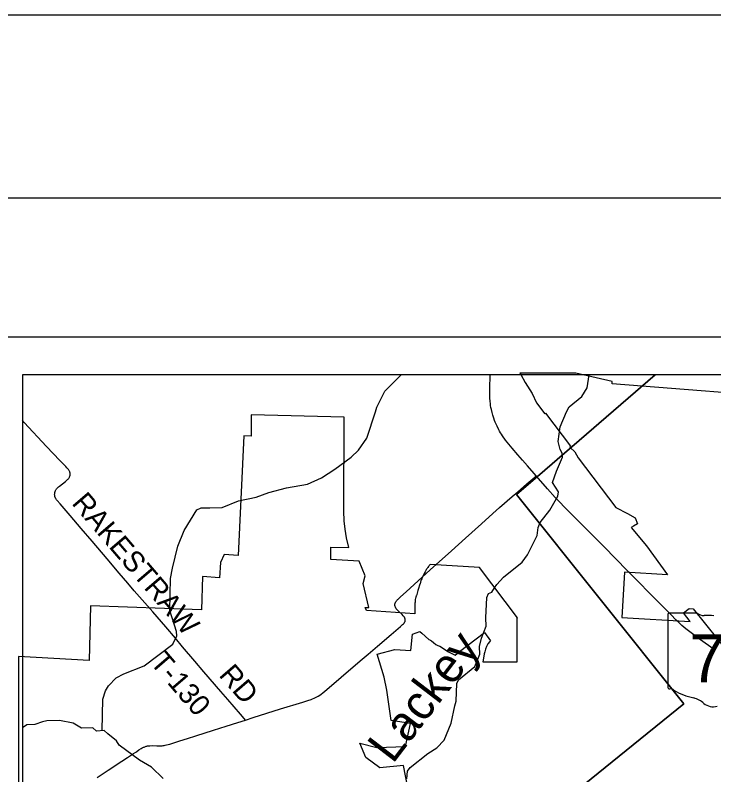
# Model space of a CAD drawing. Extents: x -5.4 to 49.9, y 13.2 to 48.4.
# Drawn here: x 26.257 to 28.171, y 46.348 to 48.429 of the extents above; entities that cross this region are included whole.
import ezdxf

# ---------------------------------------------------------------- set-up
doc = ezdxf.new("R2010")
doc.units = 0
for name, color, linetype in [('GM_X_Corporation', 7, 'Continuous'), ('GM_X_Minor_River', 7, 'Continuous'), ('GM_X_Minor_River_Text', 7, 'Continuous'), ('GM_X_State_Location', 7, 'Continuous'), ('GM_X_State_Route', 7, 'Continuous'), ('GM_X_State_Shield', 7, 'Continuous'), ('GM_X_Township', 7, 'Continuous'), ('GM_X_Township_Road', 7, 'Continuous'), ('GM_X_Township_Road_Text', 7, 'Continuous'), ('SH_Border', 7, 'Continuous'), ('SH_Cut_Line', 7, 'Continuous'), ('SH_Data', 7, 'Continuous')]:
    doc.layers.add(name, color=color, linetype=linetype)

msp = doc.modelspace()

# ---------------------------------------------------------------- linework, layer by layer
at = {"layer": 'GM_X_Corporation'}
for p, q in [((27.7927, 47.4483), (27.6398, 47.4483)), ((26.2655, 46.6728), (26.2655, 44.9832))]:
    msp.add_line(p, q, dxfattribs=at)
for points in [[(27.6398, 47.4483), (27.6425, 47.4443), (27.6547, 47.4231), (27.6735, 47.3931), (27.6855, 47.3674), (27.7081, 47.3374), (27.7103, 47.3392), (27.7787, 47.2485), (27.7764, 47.2467), (27.7778, 47.2449), (27.7899, 47.2332), (27.7998, 47.2168), (27.9024, 47.0807), (27.9348, 47.0642), (27.9553, 47.0524), (27.962, 47.0357), (27.951, 47.0294), (27.9448, 47.0254), (27.9863, 46.9755), (28.0445, 46.8962), (27.9267, 46.9035), (27.9193, 46.7796), (28.1062, 46.7686), (28.0885, 46.792), (28.1041, 46.8038), (28.1146, 46.8031), (28.2164, 46.6772)], [(28.4455, 47.4483), (28.4446, 47.4411), (28.539, 47.4366), (28.5355, 47.3724), (28.4268, 47.3772), (27.8922, 47.4191), (27.8926, 47.4253), (27.7927, 47.4483)], [(27.3326, 46.3129), (27.321, 46.3737), (27.2558, 46.3673), (27.218, 46.3961), (27.201, 46.4349), (27.2475, 46.4233), (27.3268, 46.4261), (27.3402, 46.4893), (27.2874, 46.4967), (27.2751, 46.5806), (27.2676, 46.6162), (27.249, 46.6786), (27.2972, 46.6911), (27.3408, 46.6889), (27.3451, 46.7337), (27.3657, 46.7408), (27.3713, 46.7363), (27.3907, 46.7193), (27.3951, 46.7167), (27.3973, 46.7152), (27.4028, 46.7106), (27.4099, 46.7052), (27.4153, 46.7025), (27.42, 46.7004), (27.4444, 46.6856), (27.462, 46.6763), (27.4746, 46.6863), (27.5429, 46.7377), (27.5592, 46.7155), (27.5574, 46.7138), (27.5522, 46.7075), (27.5479, 46.6997), (27.5454, 46.6925), (27.5435, 46.6856), (27.5423, 46.6795), (27.5411, 46.6734), (27.538, 46.6578), (27.6326, 46.658), (27.6322, 46.7773), (27.6336, 46.7784), (27.5294, 46.9164), (27.3944, 46.9247), (27.3914, 46.9214), (27.3902, 46.92), (27.3892, 46.9186), (27.3878, 46.9164), (27.3867, 46.9148), (27.3859, 46.9137), (27.3842, 46.9117), (27.3833, 46.9105), (27.383, 46.91), (27.3819, 46.908), (27.381, 46.9063), (27.3802, 46.9046), (27.3776, 46.8998), (27.3766, 46.898), (27.3758, 46.8962), (27.3749, 46.894), (27.3723, 46.8875), (27.3713, 46.8854), (27.3697, 46.8819), (27.3688, 46.8797), (27.3684, 46.8786), (27.3678, 46.877), (27.3671, 46.8745), (27.3665, 46.8726), (27.3651, 46.8675), (27.3622, 46.8587), (27.3604, 46.853), (27.3594, 46.8497), (27.3584, 46.8459), (27.3574, 46.8426), (27.357, 46.8415), (27.3563, 46.8396), (27.3557, 46.8384), (27.3555, 46.8377), (27.3552, 46.8371), (27.3548, 46.8359), (27.3544, 46.8344), (27.3539, 46.8318), (27.3533, 46.8285), (27.353, 46.8262), (27.3529, 46.826), (27.3527, 46.8243), (27.3524, 46.8209), (27.3522, 46.8181), (27.3521, 46.8156), (27.3518, 46.7891), (27.2197, 46.7981), (27.2162, 46.8065), (27.2255, 46.8068), (27.2103, 46.8726), (27.2154, 46.8931), (27.1997, 46.9337), (27.1217, 46.9382), (27.1219, 46.9716), (27.1713, 46.971), (27.165, 46.9976), (27.1609, 47.0207), (27.1584, 47.0438), (27.1575, 47.0708), (27.158, 47.3276), (26.9037, 47.334), (26.9031, 47.2756), (26.8837, 47.2767), (26.8681, 46.9489), (26.8297, 46.9517), (26.8196, 46.9296), (26.8166, 46.8878), (26.7705, 46.8912), (26.7674, 46.8003), (26.4629, 46.8115), (26.4596, 46.6617), (26.2655, 46.6728)]]:
    msp.add_lwpolyline(points, dxfattribs=at)
at = {"layer": 'GM_X_Minor_River'}
for points in [[(26.4952, 46.4695), (26.4969, 46.5551), (26.5041, 46.5781), (26.5123, 46.5921), (26.5331, 46.6138), (26.5545, 46.6245), (26.6102, 46.6472), (26.6892, 46.706), (26.7002, 46.7293), (26.6992, 46.7407), (26.6804, 46.798), (26.6821, 46.8864), (26.6875, 46.9144), (26.7028, 46.9746), (26.7201, 47.0172), (26.7548, 47.074), (26.7666, 47.0799), (26.7787, 47.0797), (26.7905, 47.0799), (26.8243, 47.0809), (26.8689, 47.0985), (26.9176, 47.1084), (26.9519, 47.1211), (27.0006, 47.134), (27.0577, 47.1442), (27.0962, 47.1618), (27.1326, 47.1852), (27.1779, 47.2183), (27.1975, 47.2377), (27.2208, 47.2704), (27.2442, 47.3429), (27.2482, 47.3554), (27.2701, 47.3991), (27.3148, 47.4437)], [(27.7452, 47.1236), (27.7289, 47.1485), (27.7404, 47.1802), (27.7562, 47.2187), (27.7556, 47.2289), (27.75, 47.2393), (27.7447, 47.261), (27.7498, 47.3015), (27.7675, 47.3426), (27.7746, 47.3562), (27.8095, 47.3841), (27.8243, 47.4078), (27.8294, 47.4437)], [(27.3297, 46.3375), (27.3316, 46.3579), (27.3389, 46.3685), (27.3877, 46.4065), (27.4122, 46.422), (27.4326, 46.4434), (27.4511, 46.4898), (27.4617, 46.5371), (27.4653, 46.55), (27.4672, 46.5982), (27.4719, 46.6087), (27.5161, 46.6453), (27.5302, 46.6785), (27.529, 46.7001), (27.5343, 46.7228), (27.547, 46.7553), (27.5462, 46.7785), (27.5489, 46.8338), (27.5536, 46.8452), (27.5632, 46.8488), (27.5706, 46.8601), (27.5768, 46.8699), (27.5953, 46.8893), (27.6463, 46.9307), (27.6611, 46.951), (27.6869, 47.0037), (27.6903, 47.0261), (27.6958, 47.0393), (27.7217, 47.0731), (27.7435, 47.1118), (27.7452, 47.1236)], [(26.6623, 46.3384), (26.6302, 46.3697), (26.5975, 46.388), (26.542, 46.4299), (26.5346, 46.441), (26.511, 46.4607), (26.5005, 46.47), (26.4796, 46.468), (26.4695, 46.4773), (26.4384, 46.4762), (26.4159, 46.4895), (26.3785, 46.4969), (26.3439, 46.4963), (26.3321, 46.4938), (26.3108, 46.4865), (26.2888, 46.485), (26.2771, 46.4766)]]:
    msp.add_lwpolyline(points, dxfattribs=at)
at = {"layer": 'GM_X_State_Route'}
for points in [[(27.6472, 47.2101), (27.6344, 47.2246), (27.6185, 47.2429), (27.6094, 47.2539), (27.6007, 47.2652), (27.5922, 47.2767), (27.5891, 47.2812), (27.5869, 47.285), (27.5842, 47.2896), (27.5821, 47.2936), (27.5772, 47.3036), (27.5745, 47.3091), (27.5725, 47.3141), (27.5704, 47.319), (27.5683, 47.3248), (27.5656, 47.3329), (27.5635, 47.3407), (27.5616, 47.3491), (27.5605, 47.3547), (27.5597, 47.3601), (27.5591, 47.3652), (27.5586, 47.3706), (27.5578, 47.3811), (27.5574, 47.3874), (27.5574, 47.3935), (27.5574, 47.4096), (27.5585, 47.4388), (27.5587, 47.4437)], [(28.1759, 46.6887), (28.1286, 46.723), (28.1056, 46.7399), (28.0948, 46.7483), (28.0838, 46.7573), (28.075, 46.7652), (28.0683, 46.7716), (28.053, 46.787), (28.0233, 46.8171), (27.9888, 46.852), (27.9711, 46.8703), (27.9348, 46.9069), (27.8694, 46.9734), (27.8231, 47.0203), (27.7914, 47.0518), (27.7643, 47.0792), (27.7473, 47.0965), (27.7364, 47.1083), (27.7154, 47.132), (27.6848, 47.1673), (27.6791, 47.1738), (27.6607, 47.1948), (27.6472, 47.2101)]]:
    msp.add_lwpolyline(points, dxfattribs=at)
at = {"layer": 'GM_X_State_Shield'}
for p, q in [((28.1254, 46.791), (28.0482, 46.791)), ((28.0456, 46.7875), (28.0456, 46.5874))]:
    msp.add_line(p, q, dxfattribs=at)
for centre, radius, start, end in [((28.0486, 46.788), 0.00305, 98.1301, 188.1301), ((28.1438, 46.8142), 0.0296, 231.6195, 271.1119), ((28.1536, 46.6786), 0.1064, 80.4867, 94.9883), ((28.0486, 46.587), 0.00308, 171.9584, 258.3066), ((28.0491, 46.6075), 0.0235, 267.339, 280.6039), ((28.0539, 46.5759), 0.00848, 29.7484, 93.2717), ((28.161, 46.7557), 0.2019, 240.4129, 257.1985), ((28.1008, 46.4975), 0.0632, 47.1842, 75.836), ((28.1691, 46.5749), 0.0401, 230.7004, 286.2918)]:
    msp.add_arc(centre, radius, start, end, dxfattribs=at)
at = {"layer": 'GM_X_Township'}
for points in [[(28.0105, 47.4437), (26.2771, 47.4437), (26.2771, 45.1783)], [(26.2771, 45.1783), (26.3273, 45.1524), (26.3551, 45.1388), (27.3666, 45.9579), (27.3995, 45.9845), (28.089, 46.5424), (27.6308, 47.1161), (27.6499, 47.1327), (27.6877, 47.1657), (28.0105, 47.4437)], [(28.0105, 47.4437), (27.6877, 47.1657), (27.6499, 47.1327), (27.6308, 47.1161), (28.089, 46.5424), (27.3995, 45.9845), (27.4216, 45.9826), (27.5161, 45.979), (27.573, 45.9769), (27.6274, 45.9769), (27.7195, 46.0028), (27.6935, 45.0509), (27.691, 44.9621), (27.6878, 44.8437), (27.7914, 44.8377), (29.42, 44.7443), (29.8881, 44.7175), (31.3945, 44.5822), (32.3292, 44.4982), (33.0771, 44.431)], [(33.0771, 44.431), (33.0771, 47.4437), (28.0105, 47.4437)]]:
    msp.add_lwpolyline(points, dxfattribs=at)
at = {"layer": 'GM_X_Township_Road'}
for points in [[(26.8879, 46.4983), (26.8842, 46.5026), (26.8743, 46.5145), (26.8398, 46.5545), (26.8207, 46.5766), (26.7741, 46.6308), (26.7494, 46.6596), (26.7155, 46.6992), (26.6957, 46.7224), (26.6696, 46.7532), (26.6338, 46.7945), (26.6049, 46.8279), (26.5832, 46.8526), (26.5653, 46.8733), (26.542, 46.9008), (26.509, 46.9396), (26.4676, 46.9884), (26.4376, 47.0233), (26.4077, 47.0582), (26.3797, 47.0907), (26.3719, 47.0996), (26.3702, 47.1017), (26.369, 47.1033), (26.3678, 47.1052), (26.3673, 47.1062), (26.3669, 47.107), (26.3665, 47.1081), (26.3661, 47.1091), (26.3658, 47.11), (26.3656, 47.111), (26.3654, 47.112), (26.3652, 47.1131), (26.3651, 47.1146), (26.365, 47.116), (26.365, 47.1174), (26.3651, 47.1188), (26.3652, 47.1201), (26.3654, 47.1213), (26.3656, 47.1225), (26.366, 47.1238), (26.3664, 47.1248), (26.3669, 47.1259), (26.3676, 47.1273), (26.3684, 47.1287), (26.3692, 47.13), (26.3701, 47.1312), (26.371, 47.1323), (26.372, 47.1335), (26.374, 47.1355), (26.3759, 47.1372), (26.3782, 47.1392), (26.3945, 47.1517), (26.3983, 47.1549), (26.4003, 47.1568), (26.4018, 47.1583), (26.4029, 47.1596), (26.4038, 47.1608), (26.4045, 47.1619), (26.4053, 47.1633), (26.406, 47.1646), (26.4065, 47.166), (26.4068, 47.1671), (26.4071, 47.1684), (26.4073, 47.1697), (26.4073, 47.1711), (26.4073, 47.1725), (26.4073, 47.1738), (26.4071, 47.1751), (26.4069, 47.1762), (26.4066, 47.1775), (26.4062, 47.1786), (26.4056, 47.1799), (26.405, 47.181), (26.404, 47.1826), (26.4025, 47.1844), (26.4004, 47.1871), (26.3985, 47.1893), (26.3955, 47.1924), (26.3938, 47.1942), (26.3904, 47.1978), (26.3792, 47.2096), (26.3429, 47.2479), (26.2818, 47.3133), (26.2771, 47.3183)], [(27.6339, 47.1238), (27.6585, 47.145), (27.6803, 47.1635), (27.6848, 47.1673)], [(26.8879, 46.4983), (26.9089, 46.505), (26.9835, 46.5287), (27.0447, 46.5475), (27.0589, 46.5519), (27.0678, 46.5548), (27.0719, 46.5564), (27.0759, 46.5581), (27.0798, 46.5599), (27.0837, 46.5618), (27.0872, 46.564), (27.0915, 46.5669), (27.0951, 46.5695), (27.1, 46.5732), (27.1111, 46.5822), (27.1502, 46.6159), (27.2024, 46.6609), (27.2237, 46.6791), (27.2493, 46.7007), (27.2871, 46.733), (27.3128, 46.7545), (27.3166, 46.7578), (27.3184, 46.7596), (27.3207, 46.7617), (27.3217, 46.7629), (27.3224, 46.7639), (27.3233, 46.7652), (27.3239, 46.7661), (27.3245, 46.7673), (27.325, 46.7685), (27.3254, 46.7696), (27.3256, 46.7708), (27.3258, 46.7718), (27.3258, 46.7728), (27.3257, 46.7739), (27.3256, 46.7749), (27.3253, 46.7758), (27.3249, 46.7768), (27.3244, 46.7779), (27.3238, 46.7789), (27.3232, 46.7799), (27.3224, 46.7811), (27.3211, 46.7826), (27.3199, 46.7839), (27.3168, 46.787), (27.3083, 46.7952), (27.3043, 46.7992), (27.3027, 46.8011), (27.3012, 46.8029), (27.3004, 46.8042), (27.2996, 46.8054), (27.299, 46.8066), (27.2985, 46.8078), (27.2981, 46.809), (27.2978, 46.81), (27.2975, 46.8111), (27.2974, 46.8127), (27.2974, 46.8141), (27.2974, 46.8153), (27.2975, 46.8164), (27.2978, 46.8176), (27.2981, 46.8187), (27.2986, 46.8199), (27.2994, 46.8216), (27.2999, 46.8225), (27.3004, 46.8231), (27.3014, 46.8245), (27.3023, 46.8257), (27.3035, 46.827), (27.3047, 46.8283), (27.3061, 46.8297), (27.313, 46.8358), (27.3285, 46.8497), (27.3941, 46.9094), (27.4523, 46.9618), (27.4906, 46.9963), (27.535, 47.0361), (27.5655, 47.0636), (27.584, 47.0802), (27.6185, 47.1105), (27.6339, 47.1238)], [(26.4814, 46.3406), (26.512, 46.3608), (26.5494, 46.3854), (26.5649, 46.3957), (26.5809, 46.4064), (26.5871, 46.4105), (26.5902, 46.4126), (26.5959, 46.4163), (26.6022, 46.4203), (26.6049, 46.4218), (26.607, 46.4229), (26.6088, 46.4238), (26.6102, 46.4245), (26.6119, 46.4252), (26.6138, 46.4259), (26.6154, 46.4265), (26.6174, 46.4271), (26.6191, 46.4274), (26.621, 46.4277), (26.6233, 46.4279), (26.6255, 46.4281), (26.6324, 46.4283), (26.6454, 46.4279), (26.6529, 46.4278), (26.6561, 46.4278), (26.6597, 46.4281), (26.6621, 46.4283), (26.6649, 46.4287), (26.668, 46.4292), (26.6713, 46.43), (26.6757, 46.431), (26.6803, 46.4323), (26.7076, 46.441), (26.7294, 46.4481), (26.7514, 46.4551), (26.8004, 46.4709), (26.8354, 46.4818), (26.8669, 46.4916), (26.8879, 46.4983)]]:
    msp.add_lwpolyline(points, dxfattribs=at)
at = {"layer": 'SH_Border'}
msp.add_lwpolyline([(4.2889, 47.9288), (36.2889, 47.9288), (36.2889, 26.9288), (4.2889, 26.9288)], close=True, dxfattribs=at)
at = {"layer": 'SH_Cut_Line'}
msp.add_lwpolyline([(2.7889, 26.4288), (36.7889, 26.4288), (36.7889, 48.4288), (2.7889, 48.4288)], close=True, dxfattribs=at)
at = {"layer": 'SH_Data'}
msp.add_line((26.1653, 47.5483), (33.1653, 47.5483), dxfattribs=at)

# ---------------------------------------------------------------- texts
at = {"layer": 'GM_X_Minor_River_Text'}
msp.add_text('Lackey', height=0.09472, rotation=52.5718, dxfattribs=at).set_placement((27.2912, 46.3759))
at = {"layer": 'GM_X_State_Location'}
msp.add_text('72', height=0.000189, rotation=0, dxfattribs=at).set_placement((28.1268, 46.6604))
at = {"layer": 'GM_X_State_Shield'}
msp.add_text('72', height=0.13184, dxfattribs=at).set_placement((28.1045, 46.6015))
at = {"layer": 'GM_X_Township_Road_Text'}
for s, rotation, p in [('RAKESTRAW', 310.5892, (26.4097, 47.0912)), ('T-130', 310.6308, (26.6244, 46.6552)), ('RD', 310.8141, (26.8129, 46.6204))]:
    msp.add_text(s, height=0.05682, rotation=rotation, dxfattribs=at).set_placement(p)

doc.saveas('drawing.dxf')
